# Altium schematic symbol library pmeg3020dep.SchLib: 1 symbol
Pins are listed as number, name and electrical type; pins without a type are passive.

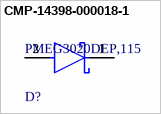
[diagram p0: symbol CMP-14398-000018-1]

## CMP-14398-000018-1
designator D?, comment PMEG3020DEP,115
DIODE SCHOTTKY 30V 2A SOD128
footprint FP-SOD128-MFG
pins: 1 C, 2 A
